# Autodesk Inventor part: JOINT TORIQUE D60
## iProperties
Created: 2004-11
Part Number: JOINT TORIQUE D60
Document SubType Name: Modeling
Designer: Bruno
Manufacturer: Standard
Standards Organization: Custom
Author: Bruno
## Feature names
1. Base1
